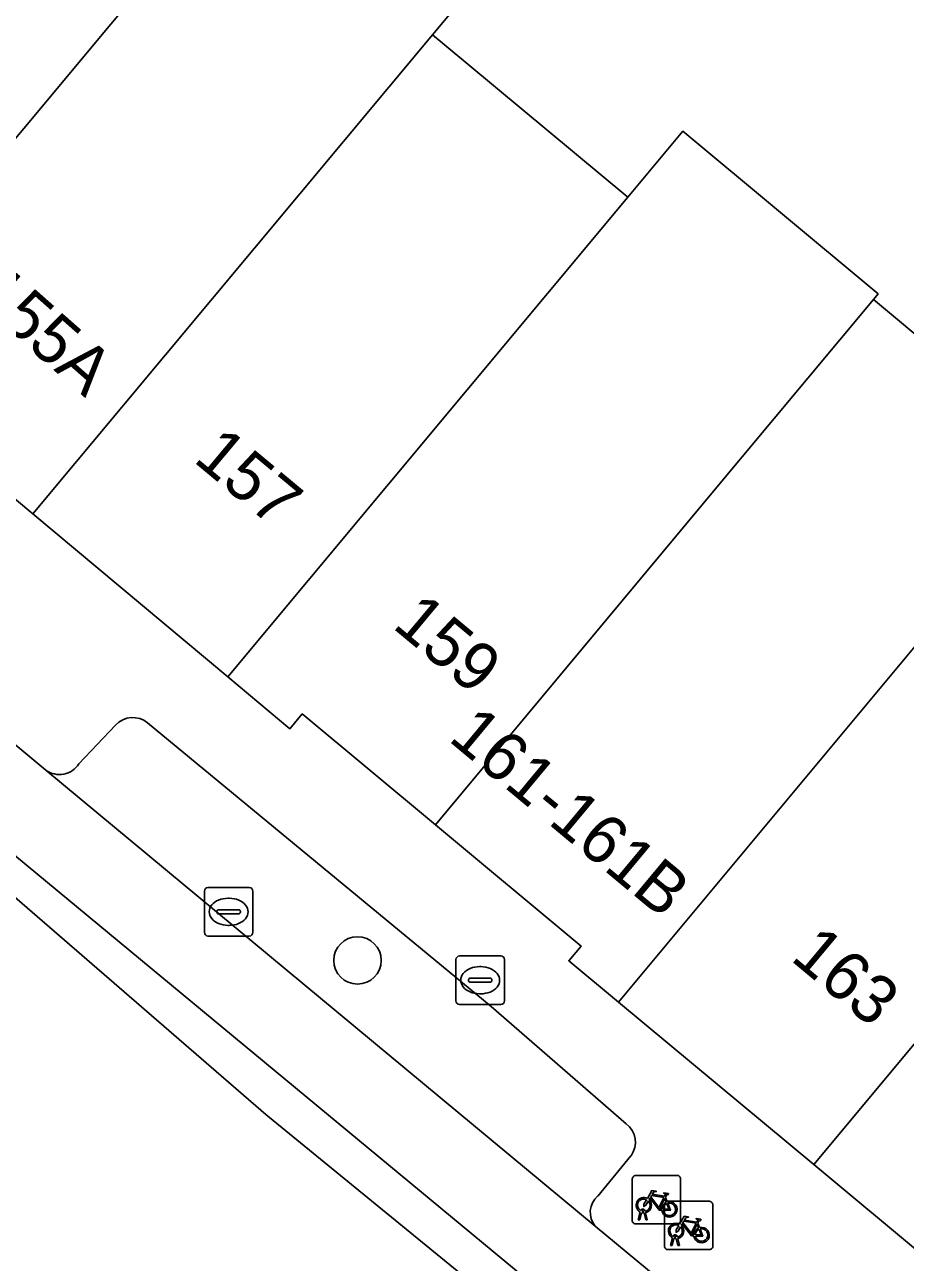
# Model space of a CAD drawing. Extents: x 162073 to 163043, y 381818 to 382561.
# Drawn here: x 162433.56 to 162451.72, y 381885.98 to 381911.5 of the extents above; entities that cross this region are included whole.
import ezdxf

# ---------------------------------------------------------------- set-up
doc = ezdxf.new("R2010")
doc.units = 0
for name, color, linetype in [('IMGEO_Boom', 7, 'Continuous'), ('IMGEO_Brandkraan', 7, 'Continuous'), ('IMGEO_Erf', 7, 'Continuous'), ('IMGEO_Fietsenrek', 7, 'Continuous'), ('IMGEO_Kolk', 7, 'Continuous'), ('IMGEO_Pand', 7, 'Continuous'), ('IMGEO_Pand_nummerreeks', 7, 'Continuous'), ('IMGEO_Parkeervlak_open', 7, 'Continuous'), ('IMGEO_Rijbaan_lokaal_gesloten', 7, 'Continuous'), ('IMGEO_Rijbaan_lokaal_open', 7, 'Continuous'), ('IMGEO_Voetpad_open', 7, 'Continuous')]:
    doc.layers.add(name, color=color, linetype=linetype)

msp = doc.modelspace()

# ---------------------------------------------------------------- linework, layer by layer
at = {"layer": 'IMGEO_Boom'}
msp.add_circle((162440.426, 381892.203), 0.489, dxfattribs=at)
at = {"layer": 'IMGEO_Brandkraan'}
for p, q in [((162442.53, 381892.295), (162443.382, 381892.295)), ((162442.455, 381891.369), (162442.455, 381892.221)), ((162442.943, 381892.075), (162442.968, 381892.075)), ((162443.456, 381892.221), (162443.456, 381891.369)), ((162442.714, 381891.789), (162442.714, 381891.801)), ((162443.152, 381891.752), (162442.754, 381891.752)), ((162442.757, 381891.838), (162443.155, 381891.838)), ((162443.198, 381891.801), (162443.198, 381891.789)), ((162442.966, 381891.515), (162442.941, 381891.515)), ((162443.382, 381891.295), (162442.53, 381891.295))]:
    msp.add_line(p, q, dxfattribs=at)
for points in [[(162442.53, 381892.295), (162443.382, 381892.295)], [(162442.455, 381891.369), (162442.455, 381892.221)], [(162443.456, 381892.221), (162443.456, 381891.369)], [(162443.382, 381891.295), (162442.53, 381891.295)]]:
    msp.add_lwpolyline(points, dxfattribs=at)
for centre, radius, start, end in [((162442.532, 381892.219), 0.0765, 91.552, 178.448), ((162442.532, 381892.219), 0.0765, 91.552, 178.448), ((162443.38, 381892.219), 0.0765, 1.552, 88.448), ((162443.38, 381892.219), 0.0765, 1.552, 88.448), ((162442.754, 381891.798), 0.0403, 85.8775, 175.7526), ((162442.751, 381891.788), 0.0366, 178.938, 274.7102), ((162443.155, 381891.795), 0.043, 264.8664, 352.4533), ((162443.159, 381891.8), 0.0386, 1.7309, 96.639), ((162442.532, 381891.371), 0.0765, 181.552, 268.448), ((162442.532, 381891.371), 0.0765, 181.552, 268.448), ((162443.38, 381891.371), 0.0765, 271.552, 358.448), ((162443.38, 381891.371), 0.0765, 271.552, 358.448)]:
    msp.add_arc(centre, radius, start, end, dxfattribs=at)
for centre, major_axis, ratio, start_param, end_param in [((162442.942, 381891.795), (-0.387, 0.002), 0.722429, 4.712389, 7.853982), ((162442.967, 381891.795), (-0.39, 0.002), 0.717154, 1.570796, 4.712389)]:
    msp.add_ellipse(centre, major_axis=major_axis, ratio=ratio, start_param=start_param, end_param=end_param, dxfattribs=at)
at = {"layer": 'IMGEO_Erf'}
msp.add_lwpolyline([(162442.882, 381912.389), (162441.973, 381911.298), (162442.173, 381911.132), (162446, 381907.945), (162447.135, 381909.306), (162451.16, 381905.95), (162451.065, 381905.836), (162455.089, 381902.482)], dxfattribs=at)
at = {"layer": 'IMGEO_Fietsenrek'}
for p, q in [((162446.089, 381886.843), (162446.089, 381887.684)), ((162446.089, 381887.684), (162446.089, 381886.843)), ((162446.164, 381887.768), (162447.005, 381887.768)), ((162447.005, 381887.768), (162446.164, 381887.768)), ((162447.089, 381887.693), (162447.089, 381886.852)), ((162447.089, 381886.852), (162447.089, 381887.693)), ((162446.754, 381886.312), (162446.754, 381887.153)), ((162446.754, 381887.153), (162446.754, 381886.312)), ((162446.776, 381887.317), (162446.812, 381887.222)), ((162446.829, 381887.237), (162447.67, 381887.237)), ((162447.67, 381887.237), (162446.829, 381887.237)), ((162447.754, 381887.162), (162447.754, 381886.321)), ((162447.754, 381886.321), (162447.754, 381887.162)), ((162446.216, 381886.852), (162446.255, 381887.012)), ((162446.285, 381887), (162446.25, 381886.852)), ((162446.327, 381887.024), (162446.326, 381887.028)), ((162446.368, 381886.852), (162446.334, 381886.994)), ((162446.358, 381887.035), (162446.359, 381887.028)), ((162446.366, 381886.998), (162446.401, 381886.852)), ((162447.014, 381886.768), (162446.173, 381886.768)), ((162446.173, 381886.768), (162447.014, 381886.768)), ((162446.25, 381886.852), (162446.216, 381886.852)), ((162446.401, 381886.852), (162446.368, 381886.852)), ((162447.441, 381886.786), (162447.477, 381886.691)), ((162446.881, 381886.321), (162446.92, 381886.481)), ((162446.95, 381886.469), (162446.915, 381886.321)), ((162446.992, 381886.493), (162446.991, 381886.497)), ((162447.033, 381886.321), (162446.999, 381886.463)), ((162447.023, 381886.504), (162447.024, 381886.497)), ((162447.031, 381886.467), (162447.066, 381886.321)), ((162447.679, 381886.237), (162446.838, 381886.237)), ((162446.838, 381886.237), (162447.679, 381886.237)), ((162446.915, 381886.321), (162446.881, 381886.321)), ((162447.066, 381886.321), (162447.033, 381886.321))]:
    msp.add_line(p, q, dxfattribs=at)
for points in [[(162446.402, 381887.294), (162446.497, 381887.458), (162446.583, 381887.444), (162446.585, 381887.435), (162446.529, 381887.424), (162446.502, 381887.379), (162446.758, 381887.338)], [(162446.758, 381887.338), (162446.783, 381887.387), (162446.777, 381887.391), (162446.754, 381887.395), (162446.742, 381887.402), (162446.741, 381887.405), (162446.743, 381887.41), (162446.838, 381887.395), (162446.84, 381887.385), (162446.83, 381887.372), (162446.818, 381887.366), (162446.804, 381887.372), (162446.776, 381887.317)], [(162446.423, 381887.242), (162446.371, 381887.152), (162446.331, 381887.127), (162446.332, 381887.174), (162446.387, 381887.268)], [(162446.698, 381887.05), (162446.648, 381887.05), (162446.457, 381887.301), (162446.438, 381887.269)], [(162446.745, 381887.313), (162446.488, 381887.354), (162446.471, 381887.325), (162446.638, 381887.105), (162446.745, 381887.313)], [(162446.793, 381887.215), (162446.763, 381887.292), (162446.654, 381887.074), (162446.697, 381887.074)], [(162446.727, 381887.074), (162446.847, 381887.073), (162446.803, 381887.187)], [(162446.823, 381887.194), (162446.878, 381887.049), (162446.728, 381887.049)], [(162447.067, 381886.763), (162447.162, 381886.927), (162447.248, 381886.913), (162447.25, 381886.904), (162447.194, 381886.893), (162447.167, 381886.848), (162447.423, 381886.807)], [(162447.088, 381886.711), (162447.036, 381886.621), (162446.996, 381886.596), (162446.997, 381886.643), (162447.052, 381886.737)], [(162447.363, 381886.519), (162447.313, 381886.519), (162447.122, 381886.77), (162447.103, 381886.738)], [(162447.41, 381886.782), (162447.153, 381886.823), (162447.136, 381886.794), (162447.303, 381886.574), (162447.41, 381886.782)], [(162447.458, 381886.684), (162447.428, 381886.761), (162447.319, 381886.543), (162447.362, 381886.543)], [(162447.392, 381886.543), (162447.512, 381886.542), (162447.468, 381886.656)], [(162447.488, 381886.663), (162447.543, 381886.518), (162447.393, 381886.518)], [(162447.423, 381886.807), (162447.448, 381886.856), (162447.442, 381886.86), (162447.419, 381886.864), (162447.407, 381886.871), (162447.406, 381886.874), (162447.408, 381886.879), (162447.503, 381886.864), (162447.505, 381886.854), (162447.495, 381886.841), (162447.483, 381886.835), (162447.469, 381886.841), (162447.441, 381886.786)]]:
    msp.add_lwpolyline(points, dxfattribs=at)
for centre, radius, start, end in [((162446.167, 381887.69), 0.0779, 92.4484, 184.2845), ((162446.167, 381887.69), 0.0779, 92.4484, 184.2845), ((162447.011, 381887.69), 0.0779, 2.4484, 94.2845), ((162447.011, 381887.69), 0.0779, 2.4484, 94.2845), ((162446.329, 381887.153), 0.159, 62.6766, 242.1369), ((162446.329, 381887.153), 0.129, 63.3192, 238.903), ((162446.329, 381887.153), 0.129, 283.6043, 43.4302), ((162446.329, 381887.153), 0.159, 283.5766, 46.6042), ((162446.856, 381887.069), 0.159, 113.3408, 178.3217), ((162446.856, 381887.069), 0.159, 187.0065, 105.7708), ((162446.856, 381887.069), 0.129, 113.923, 177.9556), ((162446.856, 381887.069), 0.129, 188.6715, 104.5883), ((162446.832, 381887.159), 0.0779, 92.4484, 184.2845), ((162446.832, 381887.159), 0.0779, 92.4484, 184.2845), ((162447.676, 381887.159), 0.0779, 2.4484, 94.2845), ((162447.676, 381887.159), 0.0779, 2.4484, 94.2845), ((162446.309, 381887.024), 0.0499, 12.8025, 158.6934), ((162446.329, 381887.153), 0.159, 253.9967, 271.7867), ((162446.309, 381887.024), 0.0174, 12.8025, 163.4502), ((162446.329, 381887.153), 0.129, 253.415, 269.0204), ((162446.167, 381886.846), 0.0779, 182.4484, 274.2845), ((162446.167, 381886.846), 0.0779, 182.4484, 274.2845), ((162446.994, 381886.622), 0.159, 62.6766, 242.1369), ((162446.994, 381886.622), 0.129, 63.3192, 238.903), ((162447.011, 381886.846), 0.0779, 272.4484, 4.2845), ((162447.011, 381886.846), 0.0779, 272.4484, 4.2845), ((162446.994, 381886.622), 0.129, 283.6043, 43.4302), ((162446.994, 381886.622), 0.159, 283.5766, 46.6042), ((162447.521, 381886.538), 0.159, 113.3408, 178.3217), ((162447.521, 381886.538), 0.159, 187.0065, 105.7708), ((162447.521, 381886.538), 0.129, 113.923, 177.9556), ((162447.521, 381886.538), 0.129, 188.6715, 104.5883), ((162446.974, 381886.493), 0.0499, 12.8025, 158.6934), ((162446.994, 381886.622), 0.159, 253.9967, 271.7867), ((162446.974, 381886.493), 0.0174, 12.8025, 163.4502), ((162446.994, 381886.622), 0.129, 253.415, 269.0204), ((162446.832, 381886.315), 0.0779, 182.4484, 274.2845), ((162446.832, 381886.315), 0.0779, 182.4484, 274.2845), ((162447.676, 381886.315), 0.0779, 272.4484, 4.2845), ((162447.676, 381886.315), 0.0779, 272.4484, 4.2845)]:
    msp.add_arc(centre, radius, start, end, dxfattribs=at)
at = {"layer": 'IMGEO_Kolk'}
for p, q in [((162437.268, 381892.78), (162437.268, 381893.632)), ((162437.343, 381893.706), (162438.195, 381893.706)), ((162438.269, 381893.632), (162438.269, 381892.78)), ((162437.756, 381893.486), (162437.781, 381893.486)), ((162437.527, 381893.2), (162437.527, 381893.212)), ((162437.965, 381893.163), (162437.567, 381893.163)), ((162437.57, 381893.249), (162437.968, 381893.249)), ((162438.011, 381893.212), (162438.011, 381893.2)), ((162437.779, 381892.926), (162437.754, 381892.926)), ((162438.195, 381892.706), (162437.343, 381892.706))]:
    msp.add_line(p, q, dxfattribs=at)
for points in [[(162437.268, 381892.78), (162437.268, 381893.632)], [(162437.343, 381893.706), (162438.195, 381893.706)], [(162438.269, 381893.632), (162438.269, 381892.78)], [(162438.195, 381892.706), (162437.343, 381892.706)]]:
    msp.add_lwpolyline(points, dxfattribs=at)
for centre, radius, start, end in [((162437.345, 381893.63), 0.0765, 91.552, 178.448), ((162437.345, 381893.63), 0.0765, 91.552, 178.448), ((162438.193, 381893.63), 0.0765, 1.552, 88.448), ((162438.193, 381893.63), 0.0765, 1.552, 88.448), ((162437.567, 381893.209), 0.0403, 85.8775, 175.7526), ((162437.564, 381893.199), 0.0366, 178.938, 274.7102), ((162437.968, 381893.206), 0.043, 264.8664, 352.4533), ((162437.972, 381893.211), 0.0386, 1.7309, 96.639), ((162437.345, 381892.782), 0.0765, 181.552, 268.448), ((162437.345, 381892.782), 0.0765, 181.552, 268.448), ((162438.193, 381892.782), 0.0765, 271.552, 358.448), ((162438.193, 381892.782), 0.0765, 271.552, 358.448)]:
    msp.add_arc(centre, radius, start, end, dxfattribs=at)
for centre, major_axis, ratio, start_param, end_param in [((162437.755, 381893.206), (-0.387, 0.002), 0.722429, 4.712389, 7.853982), ((162437.78, 381893.206), (-0.39, 0.002), 0.717154, 1.570796, 4.712389)]:
    msp.add_ellipse(centre, major_axis=major_axis, ratio=ratio, start_param=start_param, end_param=end_param, dxfattribs=at)
at = {"layer": 'IMGEO_Pand'}
for points in [[(162438.856, 381915.742), (162439.247, 381916.212), (162441.447, 381918.85), (162437.718, 381921.955), (162437.421, 381922.203), (162434.83, 381919.095), (162425.697, 381908.139), (162428.526, 381905.783), (162428.822, 381906.14), (162430.021, 381905.142)], [(162441.973, 381911.298), (162442.882, 381912.389), (162438.856, 381915.742), (162430.021, 381905.142), (162431.63, 381903.802), (162431.321, 381903.431), (162433.733, 381901.413)], [(162446, 381907.945), (162442.173, 381911.132), (162441.973, 381911.298), (162433.733, 381901.413), (162437.753, 381898.052)], [(162451.065, 381905.836), (162451.16, 381905.95), (162447.135, 381909.306), (162446, 381907.945), (162437.753, 381898.052), (162439.033, 381896.981), (162439.287, 381897.287), (162442.033, 381895.001), (162447.666, 381901.759)], [(162455.089, 381902.482), (162451.065, 381905.836), (162447.666, 381901.759), (162442.033, 381895.001), (162445.037, 381892.5), (162444.783, 381892.195), (162445.805, 381891.344)], [(162460.841, 381901.198), (162457.002, 381904.394), (162455.743, 381902.883), (162455.554, 381903.04), (162455.089, 381902.482), (162445.805, 381891.344), (162449.832, 381887.991), (162455.756, 381895.097)], [(162455.756, 381895.097), (162449.832, 381887.991), (162454.606, 381884.017), (162460.527, 381891.12), (162456.838, 381894.195), (162456.394, 381894.565), (162455.949, 381894.936)]]:
    msp.add_lwpolyline(points, close=True, dxfattribs=at)
at = {"layer": 'IMGEO_Parkeervlak_open'}
for points in [[(162445.968, 381888.832), (162443.181, 381891.25), (162436.096, 381897.104)], [(162435.435, 381897.059), (162434.683, 381896.255)], [(162434, 381896.128), (162445.326, 381886.723)], [(162445.378, 381887.343), (162446.065, 381888.174)]]:
    msp.add_lwpolyline(points, dxfattribs=at)
for centre, radius, start, end in [((162435.79, 381896.728), 0.485, 50.8086, 136.9806), ((162434.28, 381896.52), 0.482, 234.4078, 326.6593), ((162445.675, 381888.453), 0.48, 324.4929, 52.279), ((162445.674, 381887.006), 0.449, 131.2974, 219.1142)]:
    msp.add_arc(centre, radius, start, end, dxfattribs=at)
at = {"layer": 'IMGEO_Rijbaan_lokaal_gesloten'}
msp.add_lwpolyline([(162508.667, 381838.427), (162507.377, 381838.642), (162503.603, 381839.58), (162499.631, 381842.815), (162491.849, 381848.219), (162491.693, 381848.348), (162452.242, 381880.997), (162445.326, 381886.723), (162434, 381896.128), (162430.089, 381899.381), (162429.979, 381899.472), (162408.994, 381916.777), (162394.077, 381929.097), (162393.04, 381927.87), (162402.622, 381920.132), (162410.692, 381913.142), (162484.933, 381851.65), (162484.656, 381851.328), (162491.247, 381845.941), (162505.446, 381835.561), (162507.867, 381833.252)], dxfattribs=at)
at = {"layer": 'IMGEO_Rijbaan_lokaal_open'}
msp.add_lwpolyline([(162410.692, 381913.142), (162438.538, 381889.024), (162471.681, 381861.933), (162484.656, 381851.328), (162484.933, 381851.65), (162410.692, 381913.142)], dxfattribs=at)
at = {"layer": 'IMGEO_Voetpad_open'}
for points in [[(162454.606, 381884.017), (162449.832, 381887.991), (162445.805, 381891.344), (162444.783, 381892.195), (162445.037, 381892.5), (162442.033, 381895.001), (162439.287, 381897.287), (162439.033, 381896.981), (162437.753, 381898.052), (162433.733, 381901.413), (162431.321, 381903.431), (162431.63, 381903.802), (162430.021, 381905.142), (162428.822, 381906.14), (162428.526, 381905.783), (162425.697, 381908.139), (162423.449, 381910.01), (162423.767, 381910.391), (162421.988, 381911.873)], [(162429.979, 381899.472), (162430.089, 381899.381), (162434, 381896.128)], [(162436.096, 381897.104), (162443.181, 381891.25), (162445.968, 381888.832)], [(162434.683, 381896.255), (162435.435, 381897.059)], [(162446.065, 381888.174), (162445.378, 381887.343)], [(162445.326, 381886.723), (162452.242, 381880.997)]]:
    msp.add_lwpolyline(points, dxfattribs=at)
for centre, radius, start, end in [((162435.79, 381896.728), 0.485, 50.8086, 136.9806), ((162434.28, 381896.52), 0.482, 234.4078, 326.6593), ((162445.675, 381888.453), 0.48, 324.4929, 52.279), ((162445.674, 381887.006), 0.449, 131.2974, 219.1142)]:
    msp.add_arc(centre, radius, start, end, dxfattribs=at)

# ---------------------------------------------------------------- texts
at = {"layer": 'IMGEO_Pand_nummerreeks'}
for s, rotation, p in [('155-155A', 318.5637, (162430.469, 381907.636)), ('157', 320.1279, (162437.017, 381902.509)), ('159', 320.1279, (162441.121, 381899.081)), ('161-161B', 320.2195, (162442.275, 381896.751)), ('163', 320.1279, (162449.33, 381892.224))]:
    msp.add_text(s, height=1, rotation=rotation, dxfattribs=at).set_placement(p)

doc.saveas('drawing.dxf')
